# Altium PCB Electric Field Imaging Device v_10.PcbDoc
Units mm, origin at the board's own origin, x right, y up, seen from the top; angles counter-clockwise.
Board outline 57 x 55 mm, 2 copper layers (Top Layer, Bottom Layer); 81 components, 79 nets, 287 pads, 26 vias.
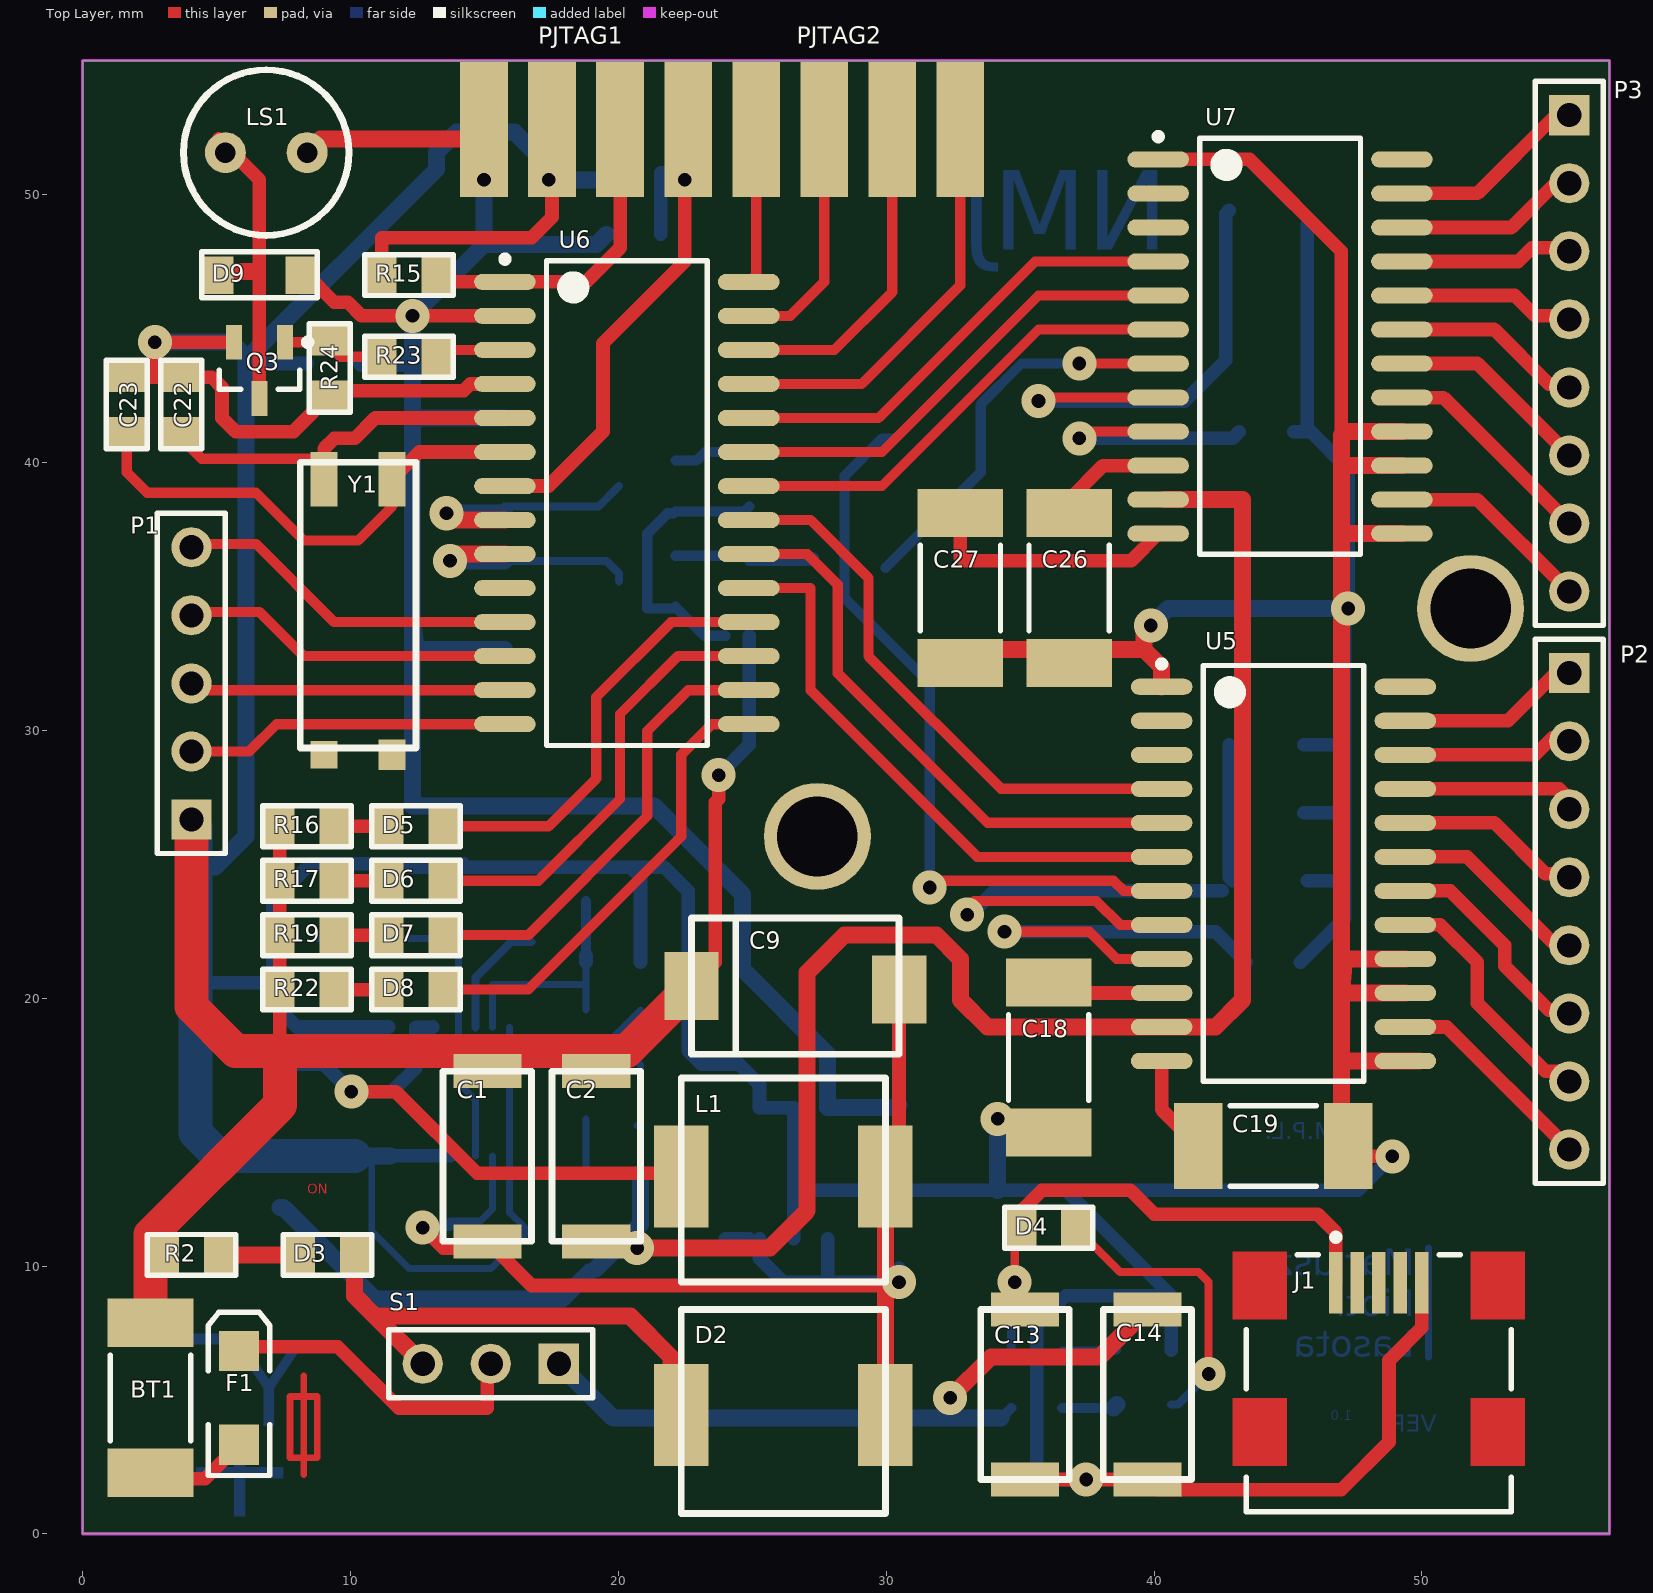
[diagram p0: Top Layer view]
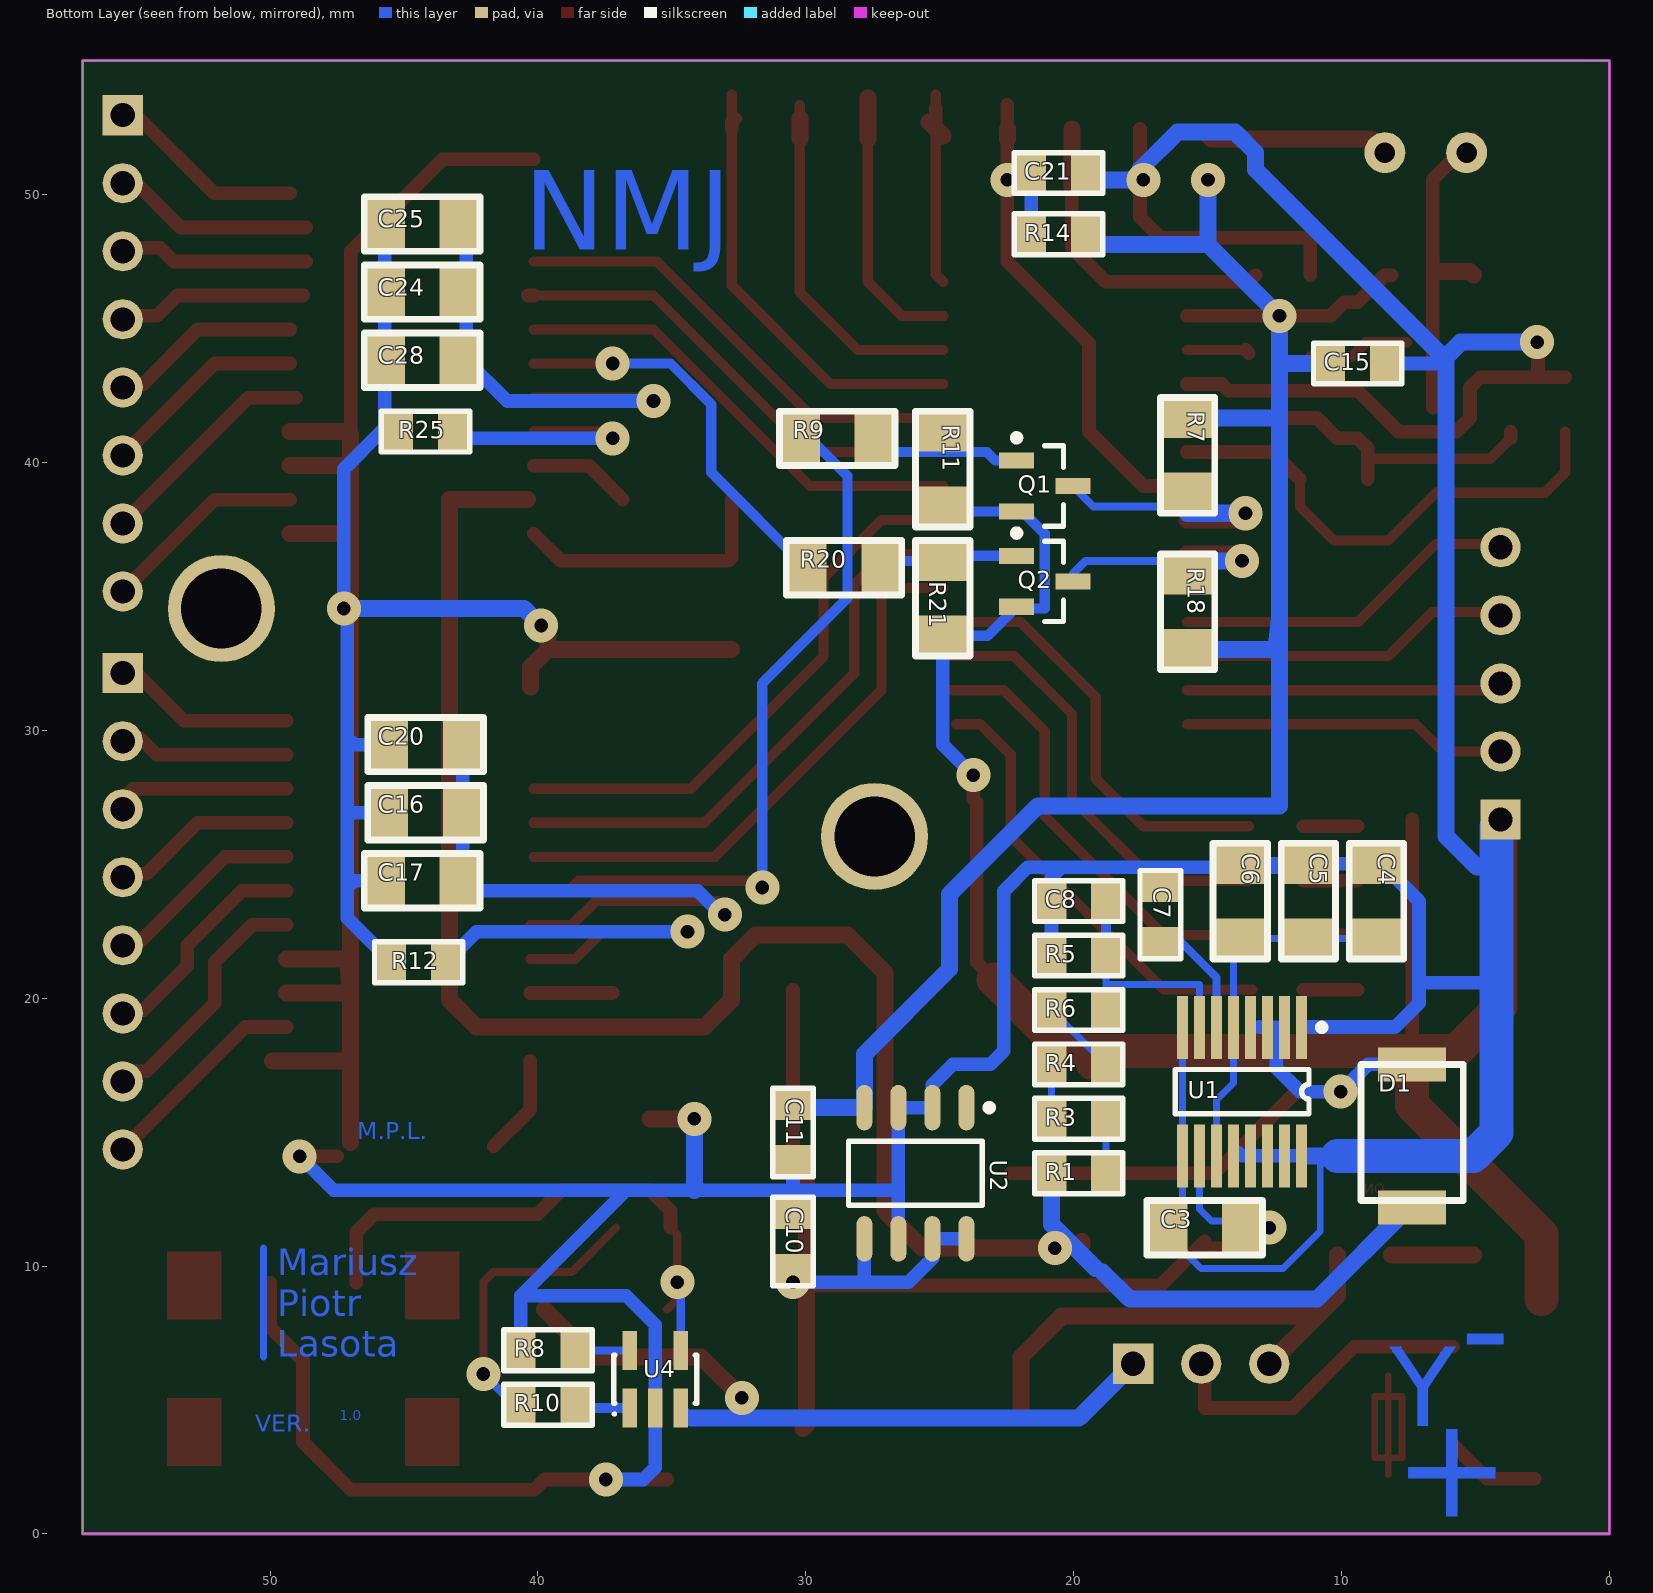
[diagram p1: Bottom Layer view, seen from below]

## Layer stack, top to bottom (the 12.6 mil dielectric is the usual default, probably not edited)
Top Layer: signal copper 0.0356
Dielectric: dielectric 0.32, FR-4, Dk 4.8
Bottom Layer: signal copper 0.0356

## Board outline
0,0 57,0 57,28 57,55 0,55 0,0

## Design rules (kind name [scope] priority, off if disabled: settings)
Clearance [All] p1 off: gap=0.203
ComponentClearance [All] p1 off: gap=0.254 collisioncheckmode=3 verticalgap=0.254 showdistances=FALSE
HoleSize [All] p1: absolutevalues=TRUE maxlimit=5.08 minlimit=0.025 maxpercent=80.000 minpercent=20.000
PolygonConnect [All] p1: connectstyle=Relief reliefconductorwidth=0.254 reliefentries=4 polygonreliefangle="90 Angle"
RoutingVias [All] p1: holewidth=0.508 width=1.27 viastyle="Through Hole" minholewidth=0.508 minwidth=1.27 maxholewidth=0.508 maxwidth=1.27
SolderMaskExpansion [All] p1: expansion=0.102
TestPointUsage [All] p1: valid=0 allowmultiple=FALSE
Testpoint [All] p1: side=15 testpointundercomponent=TRUE minsize=1.016 maxsize=2.54 preferedsize=1.524 minholesize=0 maxholesize=1.016 preferedholesize=0.813 testpointgrid=0.025 style=1023 order=0-112345678
Width [All] p1: maxlimit=2.54 minlimit=0.254 preferedwidth=0.254 minimp=50.000000 maximp=50.000000 favimp=50.000000
17 further rules are at their usual default settings.

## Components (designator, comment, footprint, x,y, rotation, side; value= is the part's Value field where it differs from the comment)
BT1 "Battery" 6332[2512] 2.54,5.08 r90 top
C1 "Cap Pol1" ##C_tantal_1 15.24,13.462 r90 top
C2 "Cap Pol1" ##C_tantal_1 19.304,13.462 r90 top
C3 "Cap" 1206 15.748,11.43 r180 bottom
C4 "Cap" 1206 8.7,24.257 r270 bottom
C5 "Cap" 1206 11.239,24.257 r270 bottom
C6 "Cap" 1206 13.779,24.257 r270 bottom
C7 "Cap" 0805 16.764,24.13 r270 bottom
C8 "Cap" 0805 20.828,23.622 r180 bottom
C9 "Cap" "C 100UF" 27.432,20.574 r90 top
C10 "Cap" 0805 30.48,11.938 r270 bottom
C11 "Cap" 0805 30.48,13.97 r90 bottom
C13 "Cap Pol1" ##C_tantal_1 35.052,5.842 r270 top
C14 "Cap Pol1" ##C_tantal_1 39.624,5.842 r270 top
C15 "Cap" 0805 8.382,43.688 r0 bottom
C16 "Cap Pol1" 1206 43.561,26.924 r0 bottom
C17 "Cap Pol1" 1206 43.688,24.384 r0 bottom
C18 "Cap Pol1" 6332[2512] 36.068,17.78 r270 top
C19 "Cap Pol1" 6332[2512] 44.45,14.478 r0 top
C20 "Cap Pol1" 1206 43.561,29.464 r0 bottom
C21 "Cap" 0805 21.59,50.8 r180 bottom
C22 "27pF" 0805 3.683,43.18 r270 top
C23 "27pF" 0805 1.651,43.18 r270 top
C24 "Cap Pol1" 1206 43.688,46.355 r0 bottom
C25 "Cap Pol1" 1206 43.688,48.895 r0 bottom
C26 "Cap Pol1" 6332[2512] 36.83,35.306 r270 top
C27 "Cap Pol1" 6332[2512] 32.766,35.306 r270 top
C28 "Cap Pol1" 1206 43.688,43.815 r0 bottom
D1 "D Schottky" ##DLAWIK_SMD_5819 7.112,14.986 r270 bottom
D2 "Diode" ##DLAWIK_SMD 25.908,5.842 r0 top
D3 "LED0" 0805 10.16,10.414 r180 top
D4 "LED0" 0805 35.052,11.43 r0 top
D5 "LED1" 0805 13.462,26.416 r180 top
D6 "LED1" 0805 13.462,24.384 r180 top
D7 "LED1" 0805 13.462,22.352 r180 top
D8 "LED1" 0805 13.462,20.32 r180 top
D9 "Diode" 0805DIODE 5.08,46.99 r0 top
F1 "800mA" 3.2X1.6X1.1 5.842,5.08 r90 top
J1 "1-1470156-1" USB_MALE 48.26,5.842 r0 top
L1 "Inductor" ##DLAWIK_SMD 26.416,11.938 r180 top
LS1 "Speaker" D_330uH_pionowy 6.858,51.562 r0 top
P1 "Header 5" HDR1X5 4.064,26.67 r90 top
P2 "Header 8" HDR1X8 55.499,32.131 r270 top
P3 "Header 8" HDR1X8 55.499,52.959 r270 top
PJTAG1 "Header 4" GOLDPIN4_2.54 14.986,52.451 r90 top
PJTAG2 "Header 4" GOLDPIN4_2.54 32.766,52.451 r270 top
Q1 "BC846B" SOT23_N 21.082,39.116 r180 bottom
Q2 "BC846B" SOT23_N 21.082,35.56 r180 bottom
Q3 "BC846B" SOT23_N 6.604,43.434 r270 top
R1 "Res1" 0805 18.796,13.462 r0 bottom
R2 "Res1" 0805 3.048,10.414 r0 top
R3 "Res1" 0805 20.828,15.494 r180 bottom
R4 "Res1" 0805 20.828,17.526 r180 bottom
R5 "Res1" 0805 20.828,21.59 r180 bottom
R6 "Res1" 0805 18.796,19.558 r0 bottom
R7 "Res1" 1206 15.748,39.624 r90 bottom
R8 "Res1" 0805 40.64,6.858 r180 bottom
R9 "Res1" 1206 28.194,40.894 r0 bottom
R10 "Res1" 0805 38.608,4.826 r0 bottom
R11 "Res1" 1206 24.892,39.116 r90 bottom
R12 "Res1" 0805 45.466,21.336 r180 bottom
R14 "Res1" 0805 21.59,48.514 r180 bottom
R15 "Res1" 0805 13.208,46.99 r180 top
R16 "Res1" 0805 7.366,26.416 r0 top
R17 "Res1" 0805 7.366,24.384 r0 top
R18 "Res1" 1206 15.748,35.052 r270 bottom
R19 "Res1" 0805 7.366,22.352 r0 top
R20 "Res1" 1206 27.94,36.068 r0 bottom
R21 "Res1" 1206 24.892,34.29 r90 bottom
R22 "Res1" 0805 7.366,20.32 r0 top
R23 "Res1" 0805 11.176,43.942 r0 top
R24 "Res1" 0805 9.228,42.502 r90 top
R25 "Res1" 0805 45.212,41.148 r180 bottom
S1 "SW-SPDT" HDR1X3 17.78,6.35 r180 top
U1 "MAX618EEE" SOP16 13.716,16.51 r0 bottom
U2 "max882" SOP8_L 25.908,13.462 r270 bottom
U4 "mcp73831" soic_MCP73831 35.56,4.826 r180 bottom
U5 "MC3494" TOUCH_PANEL 45.339,23.749 r90 top
U6 "msp430f1232" MSP430F1232 20.828,38.862 r90 top
U7 "MC3494" TOUCH_PANEL 45.212,43.434 r90 top
Y1 "XTAL" kwarc_32K 12.192,39.37 r270 top

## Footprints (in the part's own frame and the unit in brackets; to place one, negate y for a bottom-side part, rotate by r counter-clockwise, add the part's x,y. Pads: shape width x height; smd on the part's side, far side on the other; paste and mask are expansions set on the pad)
3.2X1.6X1.1 [mm] "SMT LED; 2 Flat Leads"
  rect 1.5x1.5 smd: 1(-1.75,0) 2(1.75,0)
  silkscreen extent -2.9,-1.15 3.2,1.15
0805 [mm]
  rect 1.1x1.4 smd: 1(0,0) 2(2.032,0)
  silkscreen extent -0.64,-0.76 2.67,0.76
0805DIODE [mm]
  rect 1.1x1.4 smd: 1(0,0) 2(3.048,0)
  silkscreen extent -0.64,-0.84 3.68,0.86
1206 [mm]
  rect 1.5x2 smd: 1(-0.762,0) 2(2.032,0)
  silkscreen extent -1.52,-1.02 2.79,1.02
6332[2512] [mm] "Chip Resistor; Body 6.3 x 3.2 mm (LxW typ)"
  rect 1.8x3.2 smd: 1(-2.8,0) 2(2.8,0)
  silkscreen extent -1.6,-1.5 1.6,1.5
##C_tantal_1 [mil]
  rect 50x100 smd: 1(-100,5) 2(150,5)
  silkscreen extent -100,-60 150,70
##DLAWIK_SMD [mil]
  rect 80x150 smd: 1(-140,-55) 2(160,-55)
  silkscreen extent -140,-200 160,100
##DLAWIK_SMD_5819 [mil]
  rect 50x100 smd: 1(-100,-10) 2(110,-10)
  silkscreen extent -100,-85 100,65
"C 100UF" [mil]
  rect 100x80 smd: 1(-5,185) 2(-10,-120)
  silkscreen extent -105,-120 95,185
D_330uH_pionowy [mil]
  round 60 hole 30: 1(-60,0) 2(60,0)
  silkscreen extent -122,-122 122,122
GOLDPIN4_2.54 [mil]
  rect 200x70 smd: 1(0,0) 2(0,-100) 3(0,-200) 4(0,-300)
HDR1X3 [mm] "Connector; Header; 3 Position"
  rect 1.5x1.5 hole 0.9: 1(0,0)
  round 1.5 hole 0.9: 2(2.54,0) 3(5.08,0)
  silkscreen extent -1.27,-1.27 6.35,1.27
HDR1X5 [mm] "Connector; Header; 5 Position"
  rect 1.5x1.5 hole 0.9: 1(0,0)
  round 1.5 hole 0.9: 2(2.54,0) 3(5.08,0) 4(7.62,0) 5(10.16,0)
  silkscreen extent -1.27,-1.27 11.43,1.27
HDR1X8 [mm] "Connector; Header; 8 Position"
  rect 1.5x1.5 hole 0.9: 1(0,0)
  round 1.5 hole 0.9: 2(2.54,0) 3(5.08,0) 4(7.62,0) 5(10.16,0) 6(12.7,0) 7(15.24,0) 8(17.78,0)
  silkscreen extent -1.27,-1.27 19.05,1.27
kwarc_32K [mil]
  rect 80x40 smd: 1(0,-125) 2(0,-25)
  rect 45x40 smd: 3(405,-25)
  rect 40x40 smd: 4(405,-125)
  silkscreen extent -25,-160 395,10
MSP430F1232 [mm]
  oval 0.6x2.3 smd: 1(7.874,5.058) 2(6.604,5.058) 3(5.334,5.058) 4(4.064,5.058) 5(2.794,5.058) 6(1.524,5.058) 7(0.254,5.058) 8(-1.016,5.058) 9(-2.286,5.058) 10(-3.556,5.058) 11(-4.826,5.058) 12(-6.096,5.058) 13(-7.366,5.058) 14(-8.636,5.058) 15(-8.636,-4.042) 16(-7.366,-4.042) 17(-6.096,-4.042) 18(-4.826,-4.042) 19(-3.556,-4.042) 20(-2.286,-4.042) 21(-1.016,-4.042) 22(0.254,-4.042) 23(1.524,-4.042) 24(2.794,-4.042) 25(4.064,-4.042) 26(5.334,-4.042) 27(6.604,-4.042) 28(7.874,-4.042)
  silkscreen extent -9.43,-2.49 8.85,5.18, body extent -9.44,-3.29 8.67,4.31, height 2.65
soic_MCP73831 [mm]
  rect 0.55x1.45 smd: 1(-1.011,-0.127) 2(-0.061,-0.127) 3(0.889,-0.127) 4(0.889,2.023) 5(-1.011,2.023)
  silkscreen extent -1.64,-0.4 1.49,1.85
SOP8_L [mm] "SOIC, 8-Leads, Body 4.9x3.9mm, Pitch 1.27mm, IPC High Density"
  oval 1.7x0.6 smd: 1(-2.45,1.905) 2(-2.45,0.635) 3(-2.45,-0.635) 4(-2.45,-1.905) 5(2.45,-1.905) 6(2.45,-0.635) 7(2.45,0.635) 8(2.45,1.905)
  silkscreen extent -2.57,-2.5 1.2,2.88, body extent -2,-2.5 2,2.5, height 1.75
SOP16 [mm] "SSOP; 16 Leads; Body Width 3.9 mm; Pitch 0.635 mm"
  rect 0.4x2.35 smd: 1(-2.222,-2.4) 2(-1.587,-2.4) 3(-0.953,-2.4) 4(-0.318,-2.4) 5(0.318,-2.4) 6(0.953,-2.4) 7(1.587,-2.4) 8(2.222,-2.4) 9(2.222,2.4) 10(1.587,2.4) 11(0.953,2.4) 12(0.318,2.4) 13(-0.318,2.4) 14(-0.953,2.4) 15(-1.587,2.4) 16(-2.222,2.4)
  silkscreen extent -3.1,-2.52 2.5,0.83
SOT23_N [mm] "SOT23, 3-Leads, Body 2.9x1.3mm, Pitch 0.95mm, Lead Span 2.3mm, IPC Medium Density"
  rect 1.3x0.6 smd: 1(-1.05,0.95) 2(-1.05,-0.95) 3(1.05,0)
  silkscreen extent -1.18,-1.5 0.7,1.92, body extent -0.7,-1.5 0.7,1.5, height 1.1
TOUCH_PANEL [mm]
  oval 0.6x2.3 smd: 1(7.874,5.058) 2(6.604,5.058) 3(5.334,5.058) 4(4.064,5.058) 5(2.794,5.058) 6(1.524,5.058) 7(0.254,5.058) 8(-1.016,5.058) 9(-2.286,5.058) 10(-3.556,5.058) 11(-4.826,5.058) 12(-6.096,5.058) 13(-6.096,-4.042) 14(-4.826,-4.042) 15(-3.556,-4.042) 16(-2.286,-4.042) 17(-1.016,-4.042) 18(0.254,-4.042) 19(1.524,-4.042) 20(2.794,-4.042) 21(4.064,-4.042) 22(5.334,-4.042) 23(6.604,-4.042) 24(7.874,-4.042)
  silkscreen extent -6.86,-2.49 8.85,5.18, body extent -6.86,-3.29 8.67,4.31, height 2.65
USB_MALE [mm]
  rect 0.5x2.3 smd: 1(-1.473,3.532) 2(-0.673,3.532) 3(0.127,3.532) 4(1.727,3.532) 5(0.927,3.532)
  round 0 all layers, no hole: MH1(2.327,0.932) MH2(-2.073,0.932)
  Top Layer region: -5.334,2.159 -3.302,2.159 -3.302,4.699 -5.334,4.699
  Top Layer region: -5.334,-3.302 -3.302,-3.302 -3.302,-0.762 -5.334,-0.762
  Top Layer region: 3.556,-3.302 5.588,-3.302 5.588,-0.762 3.556,-0.762
  Top Layer region: 3.556,2.159 5.588,2.159 5.588,4.699 3.556,4.699
  silkscreen extent -4.82,-5.02 5.08,5.36

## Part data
BT1: "Multicell Battery"
C1 C2 C13 C14 C16 C17 C18 C19 C20 C24 C25 C26 C27 C28: "Polarized Capacitor (Radial)"
C3 C4 C5 C6 C7 C8 C9 C10 C11 C15 C21: "Capacitor"
C22 C23: library part Cap, "Capacitor"
D1: "Schottky Diode"
D2 D9: "Default Diode"
D3 D4: "Typical INFRARED GaAs LED"
D5 D6 D7 D8: "Typical RED GaAs LED"
F1: library part "Fuse 1", "Fuse"
J1: "USB 1.1, Right Angle, Thru-Hole, B Type, Receptacle, 4 Position, White"
LS1: "Loudspeaker"
P1: "Header, 5-Pin"
P2 P3: "Header, 8-Pin"
PJTAG1 PJTAG2: "Header, 4-Pin"
Q1 Q2 Q3: library part BC850B, "NPN General-purpose Transistor"
R1 R2 R3 R4 R5 R6 R7 R8 R9 R10 R11 R12 R14 R15 R16 R17 R18 R19 R20 R21 R22 R23 R24 R25: "Resistor"
S1: "SPDT Subminiature Toggle Switch, Right Angle Mounting, Vertical Actuation"
U1: "28V, PWM, Step-UP DC-DC Converter"
Y1: "Crystal Oscillator"

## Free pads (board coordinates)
  round 4 hole 3: 0(27.432,26.035) 0(51.816,34.544)

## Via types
v1: diameter 1.27, hole 0.508, Top Layer to Bottom Layer, 26 vias

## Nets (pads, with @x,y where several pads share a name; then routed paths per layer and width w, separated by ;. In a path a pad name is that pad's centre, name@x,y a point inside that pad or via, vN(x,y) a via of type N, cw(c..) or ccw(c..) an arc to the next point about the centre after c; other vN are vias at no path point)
3.3V: C11.2 C15.2 D9.2 LS1.2 PJTAG1.1 R7.2 R14.2 R18.2 U2.4 U6.2 | length 80.5
  Top Layer w0.508: D9.2 8.382,46.99 9.398,45.974 9.906,45.974 10.414,45.466 v1(12.319,45.466) U6.2
  Top Layer w0.635: LS1.2@8.128,51.308 8.89,52.07 14.859,52.07 PJTAG1.1@14.986,52.197 ; v1(14.986,50.546) PJTAG1.1@15.113,50.419
  Bottom Layer w0.635: C15.2 12.319,43.688 ; v1@12.192,45.593 v1(12.319,45.466) ; v1(14.986,50.546) 14.986,48.133 ; R18.2 12.446,33.02 12.319,34.163 ; R7.2 12.319,41.656 ; R14.2 19.177,48.133 14.986,48.133 ; C11.2 30.39,15.912 U2.4 27.813,17.907 24.638,21.082 24.638,23.876 21.336,27.178 12.319,27.178 12.319,34.163 ; 12.319,34.163 12.319,41.656 ; 12.319,41.656 12.319,43.688 ; 12.319,43.688 v1(12.319,45.466) ; v1(12.319,45.466) 14.986,48.133
12V: C2.1 D1.2 R1.2 U5.11 U7.11 | length 75.9
  Top Layer w0.635: C2.1@19.685,10.795 19.685,10.922 19.939,10.668 v1(20.701,10.668) 25.654,10.668 27.051,12.065 27.051,20.955 28.448,22.352 31.877,22.352 32.766,21.463 32.766,19.939 33.782,18.923 42.291,18.923 43.307,19.939 43.307,38.608 U7.11@40.386,38.608
  Bottom Layer w0.635: D1.2 7.493,12.192 10.922,8.763 17.907,8.763 18.923,9.779 ; 19.177,9.906 20.828,11.557 R1.2
A1: U6.22 U7.6 | length 17.7
  Top Layer w0.381: U6.22 29.845,39.116 35.687,44.958 U7.6
A2: U5.6 U6.19 | length 21.7
  Top Layer w0.381: U6.19 27.178,35.306 27.178,31.496 33.401,25.273 U5.6@40.154,25.273
AGND: BT1.2 C1.2 C2.2 C3.1 C4.1 C5.1 C6.1 C7.1 C8.1 C9.1 C10.1 C11.1 C13.2 C14.2 C15.1 C16.2 C17.2 C18.2 C19.2 C20.2 C21.2 C22.1 C23.1 C24.2 C25.2 C26.2 C27.2 C28.2 J1.4 P1.1 PJTAG1.2 Q1.2 Q2.2 Q3.2 R2.1 R5.1 R8.1 R11.1 R12.1 R15.2 R16.1 R17.1 R19.1 R21.1 R22.1 R24.1 R25.1 U1.1 U1.8 U1.9 U1.12 U1.13 U1.14 U1.15 U1.16 U2.2 U2.3 U2.6 U4.2 U5.1 U5.13 U5.15 U5.16 U6.4 U7.1 U7.13 U7.15 U7.16 | length 424.4
  Top Layer w0.508: C23.1 2.667,43.18 ; v1@2.667,44.45 2.667,43.18 ; v1(2.701,44.484) Q3.2 ; 7.366,18.034 R22.1 7.366,22.479 7.366,24.638 R16.1@7.366,26.67 ; R15.2 11.176,48.387 16.764,48.387 17.526,49.149 PJTAG1.2 ; U6.4 14.478,42.926 14.224,42.672 9.398,42.672 7.874,41.148 5.715,41.148 5.207,41.656 5.207,42.799 4.826,43.18 C22.1 2.667,43.18 ; C9.1 22.987,20.701 23.622,21.336 23.622,27.305 23.749,27.432 v1(23.749,28.321) ; C13.2 v1(37.465,2.032) C14.2 40.132,1.651 46.99,1.651 48.768,3.429 48.768,6.477 49.987,7.696 J1.4 ; U7.1 43.561,51.308 46.99,47.879 46.99,41.021 ; C19.2@47.498,14.097 v1(48.895,14.097)
  Top Layer w0.635: C2.2 19.431,17.272 C2.2@19.558,17.399 ; C27.2@32.766,33.014 39.63,33.014 ; v1(34.163,15.494) C18.2@35.82,15.494 ; v1(39.878,33.909) 39.63,33.661 39.63,33.014 ; U5.1 40.281,32.363 39.63,33.014 ; C19.2@46.99,14.605 46.99,37.338 ; 46.99,17.78 47.244,17.653 U5.13 U5.13@49.911,17.653 ; U7.13 46.99,37.338 ; U7.15 46.99,39.878 ; U7.16 47.117,41.148 46.99,41.021 46.99,39.878 ; U5.15 46.99,20.193 47.117,21.463 U5.16 ; 46.99,37.338 46.99,39.878
  Top Layer w1.27: BT1.2@2.54,8.763 2.54,11.176 7.366,16.002 7.366,18.034 ; P1.1 4.064,19.685 5.715,18.034 7.366,18.034 ; C9.1@22.987,20.701 C9.1 20.32,18.034 7.366,18.034
  Bottom Layer w0.254: 10.795,13.97 10.795,11.303 12.192,9.906 15.24,9.906 16.51,11.176 C3.1 15.938,12.002 U1.8 ; C5.1 C6.1 ; C6.1@14.16,25.019 C6.1@14.287,25.146
  Bottom Layer w0.305: U1.1@11.43,18.923 11.443,18.91 U1.1 ; Q1.2@22.066,38.1 Q1.2
  Bottom Layer w0.381: Q1.2@22.066,38.1 21.844,38.1 21.082,37.338 21.082,34.544 22.066,34.544 Q2.2 23.214,33.528 R21.1@24.003,33.528 ; Q1.2 24.704,38.166 R11.1
  Bottom Layer w0.508: v1(2.701,44.484) v1@2.794,44.484 ; 4.211,20.574 7.112,20.574 ; 6.096,43.815 6.223,43.688 C15.1 ; U1.1@11.43,18.923 8.001,18.923 7.112,19.812 7.112,20.574 ; U1.16 U1.15 U1.14 U1.13 13.729,14.11 U1.12@13.843,14.224 ; C6.1@14.16,25.019 C6.1 C5.1 ; 16.383,24.892 18.288,24.892 ; R5.1@20.828,21.336 R5.1 C8.1 20.828,24.511 20.447,24.892 ; v1(23.749,28.321) 24.892,29.464 R21.1 ; U2.6 26.543,12.827 ; C10.1 30.48,12.827 ; C11.1 30.48,12.827 ; v1(37.465,2.032) 36.068,2.032 35.621,2.479 U4.2 35.621,7.808 36.703,8.89 40.64,8.89 ; R8.1 40.64,8.89 ; R25.1 45.847,41.148 ; R12.1 47.117,22.987 47.117,24.13 ; C16.2 46.99,26.924 47.117,27.051 ; C20.2 46.863,29.464 47.117,29.718 ; C17.2 46.863,24.384 47.117,24.13 ; C25.2 C24.2 C28.2 45.72,41.275 45.847,41.148 ; v1(48.895,14.097) 47.625,12.827 36.703,12.827 ; 7.112,20.574 7.112,23.622 8.509,25.019 C4.1 C5.1 ; C5.1 12.192,25.019 12.319,24.892 18.288,24.892 ; 18.288,24.892 20.447,24.892 ; 20.447,24.892 21.717,24.892 22.606,24.003 22.606,18.034 23.114,17.526 24.511,17.526 25.273,16.764 U2.2 U2.3 26.543,12.827 ; 26.543,12.827 30.48,12.827 ; 30.48,12.827 34.163,12.827 36.703,12.827 ; 36.703,12.827 40.64,8.89 ; 45.847,41.148 47.244,39.751 v1(47.244,34.544) 47.117,34.671 47.117,34.544 47.117,29.718 ; 47.117,24.13 47.117,27.051 ; 47.117,27.051 47.117,29.718
  Bottom Layer w0.635: v1@2.794,44.484 5.554,44.484 6.096,43.942 6.096,43.815 ; 4.211,24.892 4.953,24.892 6.096,26.035 6.096,43.815 ; 10.16,14.11 U1.16 ; v1(17.399,50.546) v1@17.526,50.546 ; C21.2 19.304,50.546 v1@17.526,50.546 ; 34.163,12.827 v1(34.163,15.494) ; v1(39.878,33.909) 40.513,34.544 47.117,34.544 v1(47.244,34.544) ; 6.096,43.815 13.208,50.927 13.208,51.562 13.97,52.324 16.129,52.324 17.526,50.927 v1@17.526,50.546
  Bottom Layer w1.27: P1.1@4.211,26.396 4.211,24.892 4.211,20.574 4.211,14.986 5.087,14.11 8.382,14.11 10.16,14.11
B1: U6.23 U7.5 | length 17.9
  Top Layer w0.381: U6.23 29.845,40.386 35.687,46.228 U7.5
  Top Layer w0.508: U7.5 U7.5@40.386,46.228
B2: U5.5 U6.20 | length 21.4
  Top Layer w0.381: U6.20 27.051,36.576 28.194,35.433 28.194,32.131 33.782,26.543 U5.5@40.154,26.543
BUZER: R23.2 U6.3 | length 2.4
  Top Layer w0.381: R23.2@13.589,44.196 U6.3
  Top Layer w0.508: R23.2@13.462,44.069 R23.2@13.589,44.196
C1: U6.24 U7.4 | length 17.7
  Top Layer w0.381: U6.24 29.718,41.656 35.56,47.498 U7.4
C2: U5.4 U6.21 | length 20.6
  Top Layer w0.381: U6.21@25.4,37.846 27.178,37.846 29.337,35.687 29.337,32.766 34.29,27.813 U5.4@40.154,27.813
CHARGER: C14.1 S1.1 U4.3 | length 27.8
  Top Layer w0.635: v1(32.385,5.08) 33.909,6.604 36.068,6.604 ; 36.449,6.604 36.068,6.604 ; C14.1 37.973,6.604 36.068,6.604
  Bottom Layer w0.381: 34.29,4.318 U4.3
  Bottom Layer w0.635: S1.1 19.812,4.318 32.385,4.318 ; v1(32.385,5.08) 32.385,4.318 ; 34.29,4.318 32.385,4.318
DATA0: P1.5 U6.11 | length 13
  Top Layer w0.381: P1.5@4.191,36.957 6.477,36.957 9.398,34.036 U6.11
  Top Layer w0.508: P1.5 P1.5@4.191,36.957
EN1: Q1.3 R7.1 U6.8 | length 9
  Top Layer w0.635: v1(13.589,38.1) 13.843,37.846 U6.8
  Bottom Layer w0.305: R7.1@15.748,38.354 19.27,38.354 Q1.3
  Bottom Layer w0.635: v1(13.589,38.1) 15.748,38.1
EN2: Q2.3 R18.1 U6.9 | length 9.5
  Top Layer w0.635: v1(13.716,36.322) 13.462,36.322 13.716,36.576 U6.9
  Bottom Layer w0.305: R18.1@15.748,36.322 19.558,36.322 20.032,35.848 Q2.3
  Bottom Layer w0.635: v1(13.716,36.322) R18.1@15.748,36.322
IRQ: P1.4 U6.12 | length 12.4
  Top Layer w0.381: P1.4@4.191,34.417 6.604,34.417 8.255,32.766 U6.12
  Top Layer w0.508: P1.4 P1.4@4.191,34.417
LED0: D5.1 U6.18 | length 16.3
  Top Layer w0.381: D5.1 17.399,26.416 19.177,28.194 19.177,31.242 21.971,34.036 U6.18
LED1: D6.1 U6.17 | length 16.9
  Top Layer w0.381: D6.1@13.335,24.511 D6.1@13.462,24.511 ; D6.1 17.018,24.384 20.066,27.432 20.066,30.607 22.225,32.766 U6.17
LED2: D7.1 U6.16 | length 17
  Top Layer w0.381: D7.1@13.335,22.225 D7.1@13.462,22.225 ; D7.1 16.637,22.352 21.082,26.797 21.082,29.972 22.606,31.496 U6.16@24.638,31.496
LED3: D8.1 U6.15 | length 16.9
  Top Layer w0.381: D8.1@13.335,20.32 D8.1 16.637,20.32 22.352,26.035 22.352,29.083 23.495,30.226 U6.15@24.384,30.226
NetBT1_1: BT1.1 F1.1 | length 3.6
  Top Layer w0.508: BT1.1@2.794,2.06 4.572,2.06 F1.1
NetC1_1: C1.1 C3.2 C9.2 C10.2 D2.2 L1.1 U1.10 U2.5 U2.7 U2.8 | length 49.3
  Top Layer w0.254: C1.1@14.859,10.668 C1.1@15.113,10.668
  Top Layer w0.508: v1(12.7,11.43) 13.462,10.668 C1.1@14.859,10.668 ; C1.1 16.764,9.271 v1@29.972,9.271 ; v1@29.972,9.144 30.226,9.144 v1(30.48,9.398) ; C9.2 30.48,13.97 L1.1@30.607,13.843
  Top Layer w0.635: L1.1 29.972,9.271 29.972,9.144 D2.2 29.972,4.064 D2.2@30.099,3.937
  Bottom Layer w0.254: v1(12.7,11.43) C3.2 13.716,11.684 14.859,11.684 15.303,12.128 U1.10
  Bottom Layer w0.508: U2.8 24.892,11.012 ; U2.7 25.273,10.287 26.162,9.398 27.813,9.398 ; U2.5 27.813,9.398 ; C10.2 C10.2@30.48,9.779 ; C10.2@30.607,9.779 C10.2@30.48,9.779 ; 27.813,9.398 v1(30.48,9.398) C10.2@30.48,9.779
NetC4_2: C4.2 C5.2 C6.2 U1.5 U1.11 | length 14
  Bottom Layer w0.254: C4.2 C5.2 ; C5.2@11.43,22.034 C5.2 ; U1.11 14.668,16.192 14.034,16.828 U1.5 14.034,22.225 C6.2 C5.2
NetC7_2: C7.2 U1.6 | length 4.5
  Bottom Layer w0.305: U1.6 14.668,20.764 16.002,22.098 C7.2
NetC13_1: C13.1 D4.1 J1.1 U4.4 | length 21.1
  Top Layer w0.305: D4.1 34.798,11.176 v1(34.798,9.398) 34.798,8.763 C13.1
  Top Layer w0.508: D4.1 35.052,12.065 35.814,12.827 39.116,12.827 40.005,11.938 46.101,11.938 46.787,11.252 J1.1
  Bottom Layer w0.305: U4.4 34.671,9.271 v1(34.798,9.398)
NetC16_1: C16.1 C17.1 C20.1 U5.8 | length 22.8
  Top Layer w0.381: v1@33.02,23.368 33.274,23.622 37.846,23.622 38.735,22.733 U5.8
  Bottom Layer w0.508: v1(33.02,23.114) 33.147,23.114 34.036,24.003 C17.1@42.545,24.003 ; C20.1 C16.1 42.799,24.511 C17.1
NetC18_1: C18.1 U5.10 | length 3.1
  Top Layer w0.508: C18.1@37.217,20.193 U5.10
NetC19_1: C19.1 U5.12 | length 3.7
  Top Layer w0.508: U5.12 40.281,15.847 C19.1
NetC22_2: C22.2 U6.5 Y1.1 | length 14.3
  Top Layer w0.381: C22.2@3.683,40.894 4.445,40.132 Y1.1@9.017,40.132
  Top Layer w0.508: C22.2@3.683,40.894 C22.2 ; Y1.1 9.017,40.132 9.017,40.513 9.398,40.894 10.16,40.894 10.922,41.656 U6.5
NetC23_2: C23.2 U6.6 Y1.2 | length 18.7
  Top Layer w0.381: C23.2 1.651,39.624 2.413,38.862 6.477,38.862 8.255,37.084 10.287,37.084 11.557,38.354 Y1.2
  Top Layer w0.508: Y1.2 12.573,40.386 U6.6
NetC24_1: C24.1 C25.1 C28.1 U7.8 | length 17.8
  Top Layer w0.381: v1@35.814,42.418 U7.8
  Top Layer w0.508: v1(35.687,42.291) v1@35.814,42.418
  Bottom Layer w0.508: v1(35.687,42.291) 41.148,42.291 42.672,43.815 42.672,49.276 C25.1@42.799,49.403
NetC26_1: C26.1 U7.10 | length 3.8
  Top Layer w0.508: C26.1@36.83,38.614 38.094,39.878 U7.10
NetC27_1: C27.1 U7.12 | length 10
  Top Layer w0.508: C27.1@32.766,38.614 32.766,36.449 32.893,36.322 39.138,36.322 U7.12
NetD1_1: D1.1 L1.2 U1.2 U1.3 U1.4 | length 21.6
  Top Layer w0.508: v1(10.033,16.51) 11.684,16.51 14.732,13.462 L1.2@22.352,13.462
  Bottom Layer w0.508: D1.1 9.017,17.526 v1(10.033,16.51) 11.557,16.51 12.446,17.399 12.446,18.91 U1.3 13.068,18.91 13.081,18.923
NetD2_1: D2.1 D3.1 S1.3 | length 18.8
  Top Layer w0.635: D3.1 10.16,8.89 10.922,8.128 ; S1.3 10.922,8.128 ; D2.1@21.971,4.572 21.971,6.604 20.447,8.128 10.922,8.128
NetD3_2: D3.2 R2.2 | length 3
  Top Layer w0.635: R2.2 D3.2
NetD4_2: D4.2 R10.2 | length 11.1
  Top Layer w0.305: D4.2 38.735,9.779 41.656,9.779 42.037,9.398 v1(42.037,5.969)
  Bottom Layer w0.305: R10.2 40.894,4.826 v1(42.037,5.969)
NetD5_2: D5.2 R16.2 | length 2
  Top Layer w0.508: R16.2 D5.2
NetD6_2: D6.2 R17.2 | length 2
  Top Layer w0.508: R17.2 D6.2
NetD7_2: D7.2 R19.2 | length 2
  Top Layer w0.508: R19.2 D7.2
NetD8_2: D8.2 R22.2 | length 2
  Top Layer w0.508: R22.2 D8.2
NetD9_1: D9.1 LS1.1 Q3.3 | length 12
  Top Layer w0.508: LS1.1@5.08,52.07 6.604,50.546 Q3.3 Q3.3@6.604,42.037
  Top Layer w0.635: D9.1 5.207,47.117 6.35,47.117
NetF1_2: F1.2 S1.2 | length 11.9
  Top Layer w0.508: F1.2@5.842,6.985 9.525,6.985 11.811,4.699 15.113,4.699 15.113,6.223 S1.2
NetP2_1: P2.1 U5.23 | length 6.8
  Top Layer w0.508: U5.23 53.213,30.353 55.118,32.258 P2.1@55.372,32.258
NetP2_2: P2.2 U5.22 | length 6.3
  Top Layer w0.508: U5.22 54.229,29.083 54.864,29.718 P2.2@55.372,29.718
NetP2_3: P2.3 U5.21 | length 6.5
  Top Layer w0.508: U5.21 55.118,27.813 P2.3@55.626,27.305
NetP2_4: P2.4 U5.20 | length 7
  Top Layer w0.508: U5.20 52.705,26.543 54.61,24.638 P2.4@55.372,24.638 ; P2.4@55.372,24.384 P2.4
NetP2_5: P2.5 U5.19 | length 7.3
  Top Layer w0.508: U5.19 51.689,25.273 54.864,22.098 P2.5@55.372,22.098
NetP2_6: P2.6 U5.18 | length 8.3
  Top Layer w0.508: U5.18 51.054,24.003 53.086,21.971 53.086,21.209 54.737,19.558 P2.6@55.372,19.558
NetP2_7: P2.7 U5.17 | length 9.3
  Top Layer w0.508: U5.17 50.673,22.733 52.07,21.336 52.07,19.812 54.61,17.272 P2.7@55.499,17.272
NetP2_8: P2.8 U5.14 | length 7.8
  Top Layer w0.508: U5.14 50.927,18.923 P2.8@55.372,14.478
NetP3_1: P3.1 U7.23 | length 7.6
  Top Layer w0.508: U7.23 52.07,50.038 54.991,52.959 P3.1@55.626,52.959
NetP3_2: P3.2 U7.22 | length 7.5
  Top Layer w0.508: U7.22@48.641,48.768 53.34,48.768 55.118,50.546 P3.2@55.372,50.546
NetP3_3: P3.3 U7.21 | length 6.9
  Top Layer w0.508: U7.21@48.641,47.498 53.594,47.498 54.102,48.006 P3.3@55.372,48.006
NetP3_4: P3.4 U7.20 | length 6.9
  Top Layer w0.508: U7.20@48.768,46.228 53.467,46.228 54.229,45.466 P3.4@55.372,45.466
NetP3_5: P3.5 U7.19 | length 7
  Top Layer w0.508: U7.19 52.705,44.958 54.737,42.926 P3.5@55.372,42.926
NetP3_6: P3.6 U7.18 | length 7.5
  Top Layer w0.508: U7.18 52.07,43.688 P3.6@55.372,40.386
NetP3_7: P3.7 U7.17 | length 8.2
  Top Layer w0.508: U7.17@49.022,42.418 50.8,42.418 P3.7@55.372,37.846
NetP3_8: P3.8 U7.14 | length 7.5
  Top Layer w0.508: U7.14 52.07,38.608 P3.8@55.372,35.306
NetPJTAG2_1: PJTAG2.1 U6.25 | length 17
  Top Layer w0.381: U6.25 29.083,42.926 32.766,46.609 PJTAG2.1@32.766,53.721
  Top Layer w0.508: PJTAG2.1@32.639,52.832 32.766,52.705 PJTAG2.1
NetPJTAG2_2: PJTAG2.2 U6.26 | length 14
  Top Layer w0.381: U6.26 28.067,44.196 30.226,46.355 PJTAG2.2@30.226,53.34
  Top Layer w0.635: PJTAG2.2@30.226,52.07 PJTAG2.2 PJTAG2.2@30.226,52.832
NetPJTAG2_3: PJTAG2.3 U6.27 | length 11.5
  Top Layer w0.381: U6.27 26.416,45.466 27.686,46.736 PJTAG2.3@27.686,53.34
  Top Layer w0.635: PJTAG2.3@27.686,52.07 PJTAG2.3 PJTAG2.3@27.686,53.594
NetQ1_1: Q1.1 R9.1 R11.2 | length 5.4
  Bottom Layer w0.381: Q1.1 22.921,40.066 23.241,40.386 24.892,40.386 R9.1@27.432,40.386
NetQ2_1: Q2.1 R20.1 R21.2 | length 5.2
  Bottom Layer w0.381: Q2.1 R21.2@24.892,36.51 ; R21.2 27.178,36.322 R20.1@27.305,36.449
NetQ3_1: Q3.1 R23.1 R24.2 | length 3.8
  Top Layer w0.381: Q3.1 9.078,44.484 9.62,43.942 R23.1
NetR3_1: R3.1 R4.1 | length 2.4
  Bottom Layer w0.254: R3.1@20.701,15.24 20.828,15.24 R3.1 R4.1
NetR4_2: R4.2 R6.2 | length 2.8
  Bottom Layer w0.254: R4.2@18.796,17.78 19.05,17.78 R6.2
NetR8_2: R8.2 U4.5 | length 2
  Bottom Layer w0.305: U4.5 38.599,6.849 R8.2
NetR9_2: R9.2 U5.7 | length 27.9
  Top Layer w0.381: v1@31.623,24.384 38.481,24.384 38.862,24.003 U5.7
  Bottom Layer w0.381: R9.2 29.845,40.894 28.448,39.497 28.448,34.925 31.623,31.75 v1(31.623,24.13)
NetR10_1: R10.1 U4.1 | length 2.1
  Bottom Layer w0.381: U4.1 R10.1@38.481,4.699
  Bottom Layer w0.635: R10.1@38.481,4.699 R10.1
NetR12_2: R12.2 U5.9 | length 15.8
  Top Layer w0.381: v1(34.417,22.479) 37.592,22.479 38.608,21.463 U5.9
  Bottom Layer w0.508: v1(34.417,22.479) 42.291,22.479 R12.2
NetR20_2: R20.2 U7.7 | length 14.8
  Top Layer w0.381: v1(37.211,43.688) U7.7
  Bottom Layer w0.381: R20.2 33.528,39.624 33.528,42.164 35.052,43.688 v1(37.211,43.688)
NetR25_2: R25.2 U7.9 | length 9.1
  Top Layer w0.381: v1@37.465,41.148 U7.9
  Top Layer w0.508: v1(37.211,40.894) v1@37.465,41.148
  Bottom Layer w0.508: v1(37.211,40.894) 42.926,40.894 R25.2
RESET: C21.1 PJTAG1.4 R14.1 U6.7 | length 21.7
  Top Layer w0.508: U6.7 17.399,39.116 19.431,41.148 19.431,44.45 22.479,47.498 PJTAG1.4@22.479,53.34
  Top Layer w0.635: PJTAG1.4@22.479,52.07 PJTAG1.4@22.479,52.451
  Bottom Layer w0.508: R14.1 C21.1 22.098,50.8 v1@22.479,50.419
  other v1: 22.479,50.546
SCL: P1.2 U6.14 | length 12.1
  Top Layer w0.381: P1.2 6.223,29.21 7.239,30.226 U6.14
SDA: P1.3 U6.13 | length 11.8
  Top Layer w0.381: P1.3@4.318,31.496 U6.13
  Top Layer w0.508: P1.3 P1.3@4.318,31.496
TDO: PJTAG2.4 U6.28 | length 8.6
  Top Layer w0.381: U6.28 25.146,47.012 PJTAG2.4@25.146,53.721
  Top Layer w0.508: PJTAG2.4 PJTAG2.4@25.146,53.213
  Top Layer w0.635: PJTAG2.4@24.87,52.175 PJTAG2.4 PJTAG2.4@25.4,52.705
TEST: PJTAG1.3 R15.1 U6.1 | length 13.2
  Top Layer w0.508: R15.1 13.462,46.736 U6.1 18.796,46.736 20.066,48.006 PJTAG1.3@20.066,51.562
  Top Layer w0.635: PJTAG1.3@20.066,50.292 PJTAG1.3
XIN: R1.1 R3.2 | length 2
  Bottom Layer w0.254: R1.1 R3.2
XOUT: C8.2 R5.2 R6.1 U1.7 | length 9.4
  Bottom Layer w0.254: U1.7 15.303,20.511 18.732,20.511 18.796,20.447 ; R6.1 18.796,20.447 ; R5.2 18.796,21.336 18.796,20.447
  Bottom Layer w0.381: R5.2 C8.2
  Bottom Layer w0.508: R5.2@18.796,21.336 R5.2
pads on no net: J1.2 J1.3 J1.5 J1.MH1 J1.MH2 U2.1 U5.2 U5.3 U5.24 U6.10 U7.2 U7.3 U7.24 Y1.3 Y1.4
copper on no net: | length 14.4
  Top Layer w0.254: 8.255,2.21 8.255,5.893 ; 7.747,2.845 8.763,2.845 8.763,5.131 8.128,5.131 7.747,5.131 7.747,2.845
  Bottom Layer w0.254: 50.241,6.604 50.241,10.668

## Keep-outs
Keep-Out Layer:
  lines w0.127: 0,0 57,0 57,55 0,55 0,0

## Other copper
Top Layer:
  text "ON" at 8.382,12.573 h0.64
Bottom Layer:
  text "NMJ" at 40.538,46.965 h5.08
  text "M.P.L." at 46.736,14.732 h0.64
  text "Mariusz" at 49.733,9.652 h1
  text "Piotr" at 49.733,8.128 h1
  text "Lasota" at 49.733,6.604 h1
  text "-" at 3.683,5.842 h3.81
  text "1.0" at 47.396,4.115 h0.64
  text "VER." at 50.546,3.81 h0.64
  text "Y" at 5.715,3.048 h5.08
  text "+" at 3.683,0.635 h3.81

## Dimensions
0,0 to 57,0 on Mechanical 1
0,0 to 0,55 on Mechanical 1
